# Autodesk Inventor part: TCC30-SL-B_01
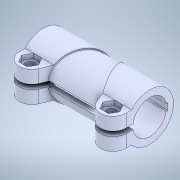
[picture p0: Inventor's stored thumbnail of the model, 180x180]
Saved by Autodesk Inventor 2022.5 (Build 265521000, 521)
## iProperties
Created: 2023-09
Part Number: TCC30-SL-B_01
Material: 一般
Document SubType Name: Modeling
Designer: ImaoCorp
Density: 1 g/cm^3
Appearance: 既定
Author: ImaoCorp
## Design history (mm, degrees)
feature "TCC30-SL-B_01"
node "ソリッド1"
